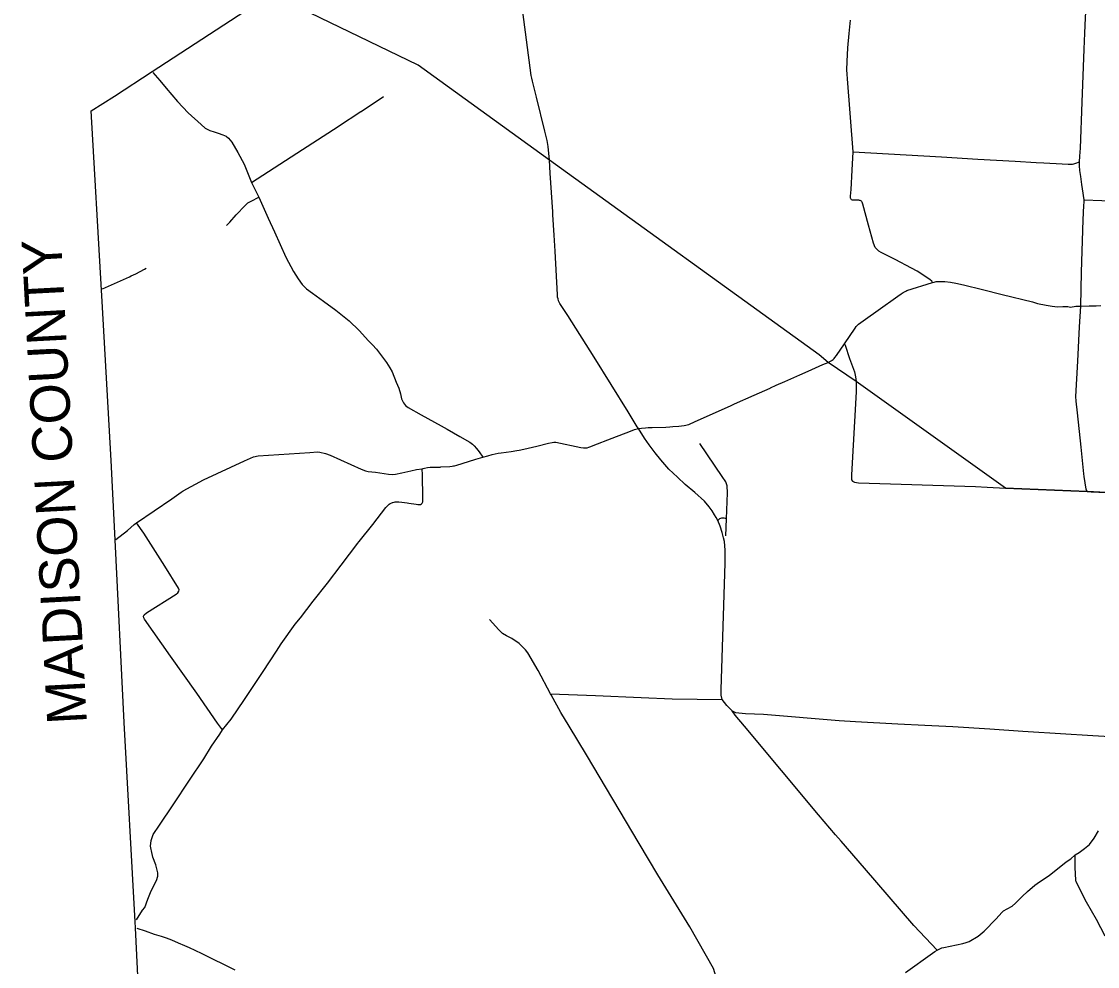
# Model space of a CAD drawing. Extents: x 1755200 to 1902939, y 644115 to 788070.
# Drawn here: x 1755807 to 1782951, y 677637 to 701476 of the extents above; entities that cross this region are included whole.
import ezdxf

# ---------------------------------------------------------------- set-up
doc = ezdxf.new("R2010")
doc.units = 0
for name, color, linetype in [('GM_X_Adjacent_County_Text', 7, 'Continuous'), ('GM_X_City_Street', 7, 'Continuous'), ('GM_X_County', 7, 'Continuous'), ('GM_X_County_Road', 7, 'Continuous'), ('GM_X_State_Route', 7, 'Continuous'), ('GM_X_Township', 7, 'Continuous'), ('GM_X_Township_Road', 7, 'Continuous')]:
    doc.layers.add(name, color=color, linetype=linetype)

msp = doc.modelspace()

# ---------------------------------------------------------------- linework, layer by layer
at = {"layer": 'GM_X_City_Street'}
msp.add_lwpolyline([(1782635, 701183), (1782651, 701570), (1782676, 702021)], dxfattribs=at)
at = {"layer": 'GM_X_County'}
msp.add_lwpolyline([(1784956, 659328), (1781576, 659434), (1779741, 659492), (1773339, 659850), (1771560, 659962), (1771157, 659994), (1759596, 661027), (1759497, 662188), (1759258, 666902), (1758681, 678614), (1758672, 678766), (1758400, 683790), (1758170, 688397), (1758072, 690399), (1757841, 694414), (1757825, 694698), (1757564, 699226), (1758151, 699596), (1759102, 700215), (1763614, 703154)], dxfattribs=at)
at = {"layer": 'GM_X_County_Road'}
for points in [[(1769211, 696603), (1769207, 696674), (1769146, 697650), (1769123, 697982), (1769092, 698322), (1769069, 698471), (1769011, 698712), (1768797, 699571), (1768694, 699972), (1768678, 700045), (1768665, 700116), (1768455, 701718), (1768288, 702977), (1767960, 705470), (1767928, 705663), (1767674, 707564), (1767277, 710453)], [(1778793, 694894), (1778771, 694925), (1778731, 694956), (1778548, 695082), (1778400, 695176), (1778261, 695257), (1777844, 695472), (1777496, 695646), (1777431, 695686), (1777390, 695722), (1777346, 695777), (1777301, 695882), (1777172, 696340), (1777029, 696868), (1777019, 696897), (1777011, 696918), (1777003, 696931), (1776994, 696943), (1776980, 696953), (1776966, 696959), (1776951, 696963), (1776931, 696965), (1776887, 696967), (1776800, 696965), (1776770, 696970), (1776746, 696980), (1776737, 696990), (1776728, 697004), (1776723, 697022), (1776723, 697070), (1776736, 697240), (1776765, 697727), (1776790, 698185), (1776641, 700029), (1776633, 700145), (1776628, 700260), (1776635, 700468), (1776657, 700816), (1776685, 701171), (1776719, 701507)], [(1782495, 697934), (1782508, 698077), (1782520, 698284), (1782567, 699439), (1782619, 700780), (1782635, 701183)], [(1759118, 700191), (1759294, 699984), (1759452, 699796), (1759742, 699454), (1760015, 699169), (1760338, 698875), (1760441, 698789), (1760561, 698723), (1760671, 698692), (1760765, 698659), (1760887, 698616), (1760969, 698580), (1761030, 698531), (1761109, 698430), (1761262, 698171), (1761420, 697873), (1761607, 697416), (1761797, 697046), (1762028, 696515), (1762193, 696174), (1762475, 695535), (1762665, 695168), (1762782, 694986), (1762885, 694840), (1762994, 694731), (1763149, 694620), (1763429, 694425), (1763735, 694193), (1764069, 693928), (1764328, 693677), (1764559, 693424), (1764661, 693319), (1764764, 693212), (1764913, 693007), (1765013, 692877), (1765097, 692743), (1765154, 692635), (1765262, 692379), (1765327, 692222), (1765370, 692084), (1765397, 691958), (1765440, 691859), (1765493, 691792), (1765563, 691736), (1765886, 691553), (1766395, 691275)], [(1776790, 698185), (1779016, 698059), (1779933, 698005), (1780878, 697949), (1781407, 697920), (1781596, 697910), (1782062, 697883), (1782209, 697877), (1782268, 697874), (1782323, 697878), (1782357, 697886), (1782402, 697901), (1782495, 697934)], [(1782619, 696976), (1782576, 697254), (1782554, 697368), (1782527, 697569), (1782504, 697719), (1782496, 697835), (1782495, 697934)], [(1782535, 694298), (1782550, 695153), (1782591, 696469), (1782608, 696832), (1782612, 696920), (1782619, 696976), (1783507, 696946), (1784356, 696907), (1784769, 696885), (1785129, 696875), (1785584, 696857), (1786091, 696836), (1786195, 696829), (1786848, 696802), (1787044, 696794)], [(1771341, 691254), (1771115, 691633), (1770257, 693004), (1769593, 694062), (1769390, 694366), (1769356, 694426), (1769342, 694480), (1769332, 694523), (1769326, 694581), (1769266, 695683), (1769242, 696082), (1769211, 696603)], [(1776566, 693348), (1776835, 693742), (1776866, 693779), (1776892, 693811), (1776921, 693840), (1777096, 693969), (1777418, 694197), (1777917, 694549), (1778001, 694610), (1778050, 694642), (1778083, 694660), (1778113, 694675), (1778142, 694687), (1778793, 694894), (1778835, 694903)], [(1778835, 694903), (1778879, 694913), (1779104, 694913), (1779240, 694903), (1779381, 694871), (1779573, 694829), (1780049, 694712), (1780543, 694593), (1781309, 694400), (1781440, 694366), (1781655, 694317), (1781808, 694291), (1781940, 694282), (1782079, 694283), (1782199, 694290), (1782270, 694273), (1782405, 694291), (1782535, 694298)], [(1782535, 694298), (1782745, 694300), (1782920, 694307), (1783033, 694312)], [(1776251, 692927), (1776255, 692929), (1776280, 692948), (1776304, 692973), (1776325, 692999), (1776363, 693054), (1776566, 693348)], [(1774706, 692237), (1774843, 692298), (1775060, 692395), (1775439, 692564), (1775649, 692658), (1776021, 692821), (1776156, 692877), (1776219, 692908), (1776251, 692927)], [(1773694, 691781), (1773797, 691827), (1774289, 692049), (1774690, 692229), (1774706, 692237)], [(1768358, 690662), (1768483, 690686), (1768811, 690760), (1769103, 690838), (1769190, 690858), (1769240, 690864), (1769283, 690866), (1769921, 690727), (1769986, 690717), (1770030, 690718), (1770075, 690722), (1770123, 690737), (1770169, 690754), (1770226, 690777), (1770706, 690962), (1771174, 691144), (1771272, 691184), (1771368, 691209), (1771448, 691220), (1771547, 691228), (1771615, 691230), (1771714, 691235), (1772065, 691244), (1772161, 691249), (1772240, 691256), (1772393, 691269), (1772527, 691282), (1772563, 691289), (1772598, 691297), (1772640, 691312), (1772799, 691382), (1773694, 691781)], [(1766395, 691275), (1766548, 691191), (1766861, 691006), (1767113, 690862), (1767182, 690812), (1767229, 690772), (1767288, 690708), (1767355, 690619), (1767442, 690488)], [(1773556, 687811), (1773557, 687833), (1773562, 688067), (1773561, 688136), (1773540, 688359), (1773520, 688449), (1773486, 688588), (1773435, 688744), (1773371, 688887), (1773328, 688967), (1773293, 689031), (1773233, 689129), (1773156, 689234), (1773037, 689374), (1772791, 689590), (1772546, 689792), (1772359, 689981), (1772141, 690185), (1771936, 690415), (1771790, 690595), (1771640, 690799), (1771526, 690968), (1771368, 691209), (1771341, 691254)], [(1758190, 688407), (1758479, 688638), (1758648, 688783), (1758710, 688829), (1759599, 689437), (1759837, 689604), (1759887, 689640), (1760396, 689910), (1761431, 690392), (1761660, 690495), (1761773, 690522), (1763081, 690607), (1763271, 690616), (1763329, 690612), (1763472, 690575), (1763593, 690533), (1764374, 690183), (1764486, 690140), (1764554, 690126), (1764734, 690110), (1765064, 690056), (1765178, 690052), (1765245, 690059), (1765402, 690091), (1765631, 690139), (1765775, 690171), (1765914, 690192)], [(1767267, 690431), (1767442, 690488), (1767569, 690522), (1767682, 690553), (1767828, 690587), (1767909, 690597), (1768158, 690628), (1768301, 690652), (1768358, 690662)], [(1766706, 690265), (1766732, 690270), (1766792, 690286), (1767243, 690423), (1767267, 690431)], [(1765534, 689330), (1765581, 689323), (1765761, 689299), (1765801, 689293), (1765840, 689290), (1765871, 689293), (1765901, 689306), (1765915, 689322), (1765925, 689339), (1765928, 689362), (1765932, 689383), (1765933, 689417), (1765927, 689661), (1765922, 689841), (1765921, 689916), (1765919, 690042), (1765914, 690192)], [(1765914, 690192), (1765943, 690200), (1765975, 690208), (1766049, 690224), (1766117, 690233), (1766195, 690236), (1766368, 690236), (1766389, 690238)], [(1766389, 690238), (1766611, 690250), (1766671, 690257), (1766706, 690265)], [(1764315, 688347), (1764323, 688357), (1764668, 688790), (1765000, 689215), (1765046, 689269), (1765084, 689300), (1765107, 689315), (1765145, 689334), (1765168, 689343)], [(1765168, 689343), (1765174, 689345), (1765212, 689353), (1765234, 689357), (1765251, 689358), (1765270, 689358), (1765298, 689358), (1765328, 689356), (1765402, 689347), (1765534, 689330)], [(1759077, 680590), (1759061, 680668), (1759078, 680818), (1759131, 680968), (1759287, 681203), (1759631, 681711), (1760047, 682335), (1760404, 682872), (1760596, 683193), (1760806, 683496), (1760873, 683608), (1761094, 683872), (1761429, 684371), (1761902, 685082), (1762236, 685589), (1762361, 685777), (1762710, 686270), (1762844, 686434), (1763167, 686851), (1763522, 687306), (1763867, 687757), (1764291, 688315), (1764315, 688347)], [(1773735, 684084), (1773599, 684221), (1773485, 684370), (1773460, 684482), (1773459, 684627), (1773556, 687811)], [(1773735, 684084), (1773770, 684068), (1773823, 684048), (1774075, 684022), (1774528, 683999), (1776435, 683842), (1776845, 683820), (1777912, 683762), (1778599, 683726), (1779300, 683688), (1780237, 683632), (1781070, 683572), (1781206, 683562), (1782831, 683463), (1783987, 683396)], [(1778904, 678047), (1778314, 678671), (1777693, 679394), (1777072, 680120), (1776484, 680798), (1776345, 680960), (1775913, 681464), (1774048, 683702), (1773810, 683978), (1773735, 684084)], [(1778110, 677485), (1778787, 677975), (1778847, 678015), (1778904, 678047), (1778937, 678067), (1778976, 678084), (1779027, 678103), (1779075, 678117), (1779556, 678216), (1779642, 678244), (1779710, 678267), (1779941, 678398), (1780096, 678528), (1780393, 678836), (1780538, 679000), (1780582, 679037), (1780675, 679091), (1780795, 679160), (1780886, 679237), (1781055, 679404), (1781184, 679531), (1781374, 679692), (1781486, 679771), (1781728, 679931), (1782163, 680280), (1782279, 680349), (1782391, 680450), (1782493, 680516), (1782627, 680609), (1782752, 680718), (1782868, 680877), (1782977, 681061)], [(1759063, 679504), (1759105, 679598), (1759208, 679807), (1759243, 679915), (1759244, 680001), (1759197, 680198), (1759119, 680391), (1759084, 680555), (1759077, 680590)], [(1783142, 678403), (1782923, 678824), (1782676, 679262), (1782411, 679769), (1782409, 679811), (1782392, 680130), (1782391, 680450)], [(1758707, 678813), (1758861, 679055), (1758919, 679123), (1758993, 679335), (1759023, 679416), (1759045, 679464), (1759063, 679504)]]:
    msp.add_lwpolyline(points, dxfattribs=at)
at = {"layer": 'GM_X_State_Route'}
msp.add_lwpolyline([(1758718, 678605), (1758924, 678536), (1759155, 678456), (1759328, 678400), (1759455, 678358), (1759590, 678309), (1759762, 678235), (1759915, 678170), (1760033, 678118), (1760182, 678048), (1760356, 677962), (1761185, 677549)], dxfattribs=at)
at = {"layer": 'GM_X_Township'}
msp.add_lwpolyline([(1794587, 689062), (1792546, 689167), (1791461, 689213), (1784810, 689542), (1784632, 689548), (1783167, 689596), (1782688, 689618), (1780628, 689706), (1776861, 692396), (1776156, 692877), (1775926, 693071), (1769123, 697982), (1765814, 700371), (1762103, 702170)], dxfattribs=at)
at = {"layer": 'GM_X_Township_Road'}
for points in [[(1764374, 699207), (1764942, 699581)], [(1763805, 698834), (1764369, 699204), (1764374, 699207)], [(1761607, 697416), (1762893, 698246), (1763796, 698828), (1763805, 698834)], [(1760978, 696327), (1761064, 696416), (1761226, 696601), (1761447, 696837), (1761519, 696901), (1761600, 696946), (1761797, 697046)], [(1758575, 695056), (1758693, 695112), (1758910, 695231), (1758955, 695252)], [(1757848, 694731), (1758534, 695036), (1758575, 695056)], [(1782688, 689618), (1782668, 689681), (1782617, 689999), (1782609, 690063), (1782536, 690737), (1782447, 691605), (1782411, 691896), (1782406, 692012), (1782453, 692906), (1782501, 693776), (1782535, 694298)], [(1776566, 693348), (1776587, 693314), (1776697, 692972), (1776817, 692640), (1776847, 692515), (1776861, 692398)], [(1776861, 692398), (1776861, 692396), (1776867, 692135), (1776747, 690039), (1776743, 689967), (1776746, 689913), (1776770, 689877), (1776818, 689853), (1776920, 689842), (1779873, 689745), (1780168, 689730)], [(1773576, 688500), (1773591, 688930), (1773616, 689588), (1773609, 689759), (1773571, 689859), (1773483, 689996), (1772919, 690827)], [(1780168, 689730), (1780628, 689706), (1782688, 689618)], [(1782688, 689618), (1782688, 689618), (1782793, 689613)], [(1782793, 689613), (1783167, 689596), (1783370, 689590)], [(1773371, 688887), (1773405, 688925), (1773427, 688934), (1773450, 688944), (1773471, 688951), (1773505, 688954), (1773530, 688953), (1773565, 688946), (1773591, 688930)], [(1760873, 683608), (1760748, 683778), (1760228, 684530), (1759563, 685466), (1758910, 686401), (1758892, 686435), (1758888, 686477), (1758903, 686509), (1758959, 686555), (1759709, 687030), (1759753, 687066), (1759775, 687106), (1759784, 687140), (1759768, 687184), (1759419, 687739), (1758893, 688570), (1758710, 688829)], [(1769171, 684488), (1769155, 684519), (1768844, 685102), (1768584, 685546), (1768524, 685625), (1768359, 685784), (1768174, 685907), (1768040, 685982), (1767938, 686041), (1767845, 686127), (1767612, 686391)], [(1769155, 684519), (1770290, 684471), (1771437, 684422), (1772218, 684388), (1773485, 684370)], [(1774429, 674407), (1774188, 674926), (1774139, 675101), (1774091, 675155), (1774025, 675200), (1773798, 675535), (1773663, 676229), (1773462, 676936), (1773264, 677586), (1772665, 678633), (1771860, 679950), (1771386, 680739), (1770061, 682979), (1769620, 683702), (1769410, 684045), (1769171, 684488)]]:
    msp.add_lwpolyline(points, dxfattribs=at)

# ---------------------------------------------------------------- texts
at = {"layer": 'GM_X_Adjacent_County_Text'}
msp.add_text('MADISON COUNTY', height=1000, rotation=93.0522, dxfattribs=at).set_placement((1757457, 683771))

doc.saveas('drawing.dxf')
